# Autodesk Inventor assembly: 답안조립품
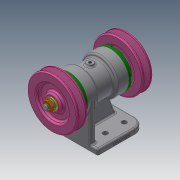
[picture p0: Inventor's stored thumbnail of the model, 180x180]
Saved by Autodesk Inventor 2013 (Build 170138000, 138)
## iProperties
Created: 2020-06
Part Number: 답안조립품
Document SubType Name: Assembly
Designer: 19
Author: 19
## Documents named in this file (12)
- C:\Users\user\Desktop\700606V1040\답안조립품.iam
- C:\Users\user\Desktop\700606V1040\본체.ipt
- C:\Users\user\Desktop\700606V1040\Ű 5x5x12.ipt
- C:\Users\user\Desktop\700606V1040\V-벨트풀리.ipt
- C:\Users\user\Desktop\700606V1040\너트 M10.ipt
- C:\Users\user\Desktop\700606V1040\베어링 6204.ipt
- C:\Users\user\Desktop\700606V1040\볼트 M4.ipt
- C:\Users\user\Desktop\700606V1040\스프링 와셔 10.ipt
- C:\Users\user\Desktop\700606V1040\오일 실 20 32 5.ipt
- C:\Users\user\Desktop\700606V1040\축.ipt
- C:\Users\user\Desktop\700606V1040\커버.ipt
- C:\Users\user\Desktop\700606V1040\평면 와셔 10x21.ipt
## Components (4 placed, 2 different names)
1. Ű 5x5x12:1
2. V-벨트풀리:1
3. Ű 5x5x12:2
4. V-벨트풀리:2
